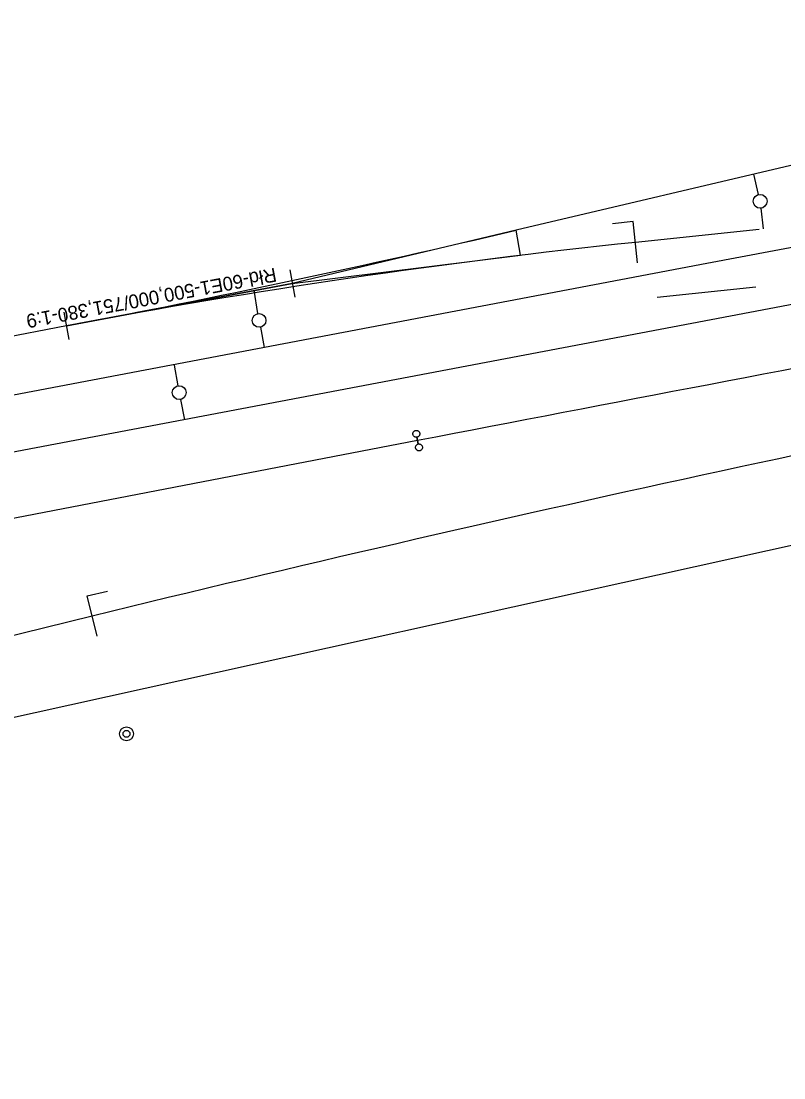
# Model space of a CAD drawing. Extents: x 6540402 to 6566579, y 5525343 to 5532423.
# Drawn here: x 6558407.9 to 6558463, y 5528815.2 to 5528891.5 of the extents above; entities that cross this region are included whole.
import ezdxf

# ---------------------------------------------------------------- set-up
doc = ezdxf.new("R2010")
doc.units = 0
for name, color, linetype in [('IR_ps_geometria', 7, 'Continuous'), ('TOR_PS_ODW-studnie betonowe', 7, 'Continuous'), ('TOR_PS_OPIS_T-symbole geometrii', 7, 'Continuous'), ('TOR_PS_OPIS_T-ukresy', 7, 'Continuous'), ('TOR_PS_T-rozjazdy projektowane', 7, 'Continuous'), ('TOR_PS_T-tory projektowane', 7, 'Continuous')]:
    doc.layers.add(name, color=color, linetype=linetype)

msp = doc.modelspace()

# ---------------------------------------------------------------- linework, layer by layer
at = {"layer": 'IR_ps_geometria'}
msp.add_lwpolyline([(6558436.522, 5528861.25), (6558436.569, 5528861.005), (6558436.602, 5528861.009), (6558436.634, 5528861.009), (6558436.667, 5528861.004), (6558436.698, 5528860.996), (6558436.728, 5528860.983), (6558436.757, 5528860.966), (6558436.782, 5528860.946), (6558436.805, 5528860.923), (6558436.825, 5528860.897), (6558436.841, 5528860.869), (6558436.854, 5528860.838), (6558436.862, 5528860.807), (6558436.866, 5528860.774), (6558436.866, 5528860.741), (6558436.861, 5528860.709), (6558436.853, 5528860.678), (6558436.84, 5528860.647), (6558436.823, 5528860.619), (6558436.803, 5528860.593), (6558436.78, 5528860.57), (6558436.754, 5528860.551), (6558436.725, 5528860.534), (6558436.695, 5528860.522), (6558436.664, 5528860.514), (6558436.631, 5528860.51), (6558436.598, 5528860.51), (6558436.566, 5528860.515), (6558436.534, 5528860.523), (6558436.504, 5528860.536), (6558436.476, 5528860.552), (6558436.45, 5528860.572), (6558436.427, 5528860.596), (6558436.408, 5528860.622), (6558436.391, 5528860.65), (6558436.379, 5528860.681), (6558436.371, 5528860.712), (6558436.367, 5528860.745), (6558436.367, 5528860.777), (6558436.371, 5528860.81), (6558436.38, 5528860.841), (6558436.393, 5528860.871), (6558436.409, 5528860.9), (6558436.429, 5528860.925), (6558436.453, 5528860.948), (6558436.479, 5528860.968), (6558436.507, 5528860.984), (6558436.538, 5528860.997), (6558436.569, 5528861.005), (6558436.475, 5528861.496), (6558436.442, 5528861.492), (6558436.41, 5528861.492), (6558436.377, 5528861.497), (6558436.346, 5528861.505), (6558436.316, 5528861.518), (6558436.287, 5528861.534), (6558436.262, 5528861.555), (6558436.239, 5528861.578), (6558436.219, 5528861.604), (6558436.203, 5528861.632), (6558436.19, 5528861.663), (6558436.182, 5528861.694), (6558436.178, 5528861.727), (6558436.178, 5528861.759), (6558436.183, 5528861.792), (6558436.191, 5528861.823), (6558436.204, 5528861.853), (6558436.221, 5528861.882), (6558436.241, 5528861.907), (6558436.264, 5528861.93), (6558436.29, 5528861.95), (6558436.318, 5528861.966), (6558436.349, 5528861.979), (6558436.38, 5528861.987), (6558436.413, 5528861.991), (6558436.446, 5528861.991), (6558436.478, 5528861.986), (6558436.509, 5528861.978), (6558436.54, 5528861.965), (6558436.568, 5528861.948), (6558436.594, 5528861.928), (6558436.617, 5528861.905), (6558436.636, 5528861.879), (6558436.652, 5528861.851), (6558436.665, 5528861.82), (6558436.673, 5528861.789), (6558436.677, 5528861.756), (6558436.677, 5528861.723), (6558436.672, 5528861.691), (6558436.664, 5528861.66), (6558436.651, 5528861.629), (6558436.635, 5528861.601), (6558436.614, 5528861.575), (6558436.591, 5528861.552), (6558436.565, 5528861.533), (6558436.537, 5528861.516), (6558436.506, 5528861.504), (6558436.475, 5528861.496)], close=True, dxfattribs=at)
msp.add_lwpolyline([(6558436.522, 5528861.25), (6558436.569, 5528861.005), (6558436.602, 5528861.009), (6558436.634, 5528861.009), (6558436.667, 5528861.004), (6558436.698, 5528860.996), (6558436.728, 5528860.983), (6558436.757, 5528860.966), (6558436.782, 5528860.946), (6558436.805, 5528860.923), (6558436.825, 5528860.897), (6558436.841, 5528860.869), (6558436.854, 5528860.838), (6558436.862, 5528860.807), (6558436.866, 5528860.774), (6558436.866, 5528860.741), (6558436.861, 5528860.709), (6558436.853, 5528860.678), (6558436.84, 5528860.647), (6558436.823, 5528860.619), (6558436.803, 5528860.593), (6558436.78, 5528860.57), (6558436.754, 5528860.551), (6558436.725, 5528860.534), (6558436.695, 5528860.522), (6558436.664, 5528860.514), (6558436.631, 5528860.51), (6558436.598, 5528860.51), (6558436.566, 5528860.515), (6558436.534, 5528860.523), (6558436.504, 5528860.536), (6558436.476, 5528860.552), (6558436.45, 5528860.572), (6558436.427, 5528860.596), (6558436.408, 5528860.622), (6558436.391, 5528860.65), (6558436.379, 5528860.681), (6558436.371, 5528860.712), (6558436.367, 5528860.745), (6558436.367, 5528860.777), (6558436.371, 5528860.81), (6558436.38, 5528860.841), (6558436.393, 5528860.871), (6558436.409, 5528860.9), (6558436.429, 5528860.925), (6558436.453, 5528860.948), (6558436.479, 5528860.968), (6558436.507, 5528860.984), (6558436.538, 5528860.997), (6558436.569, 5528861.005), (6558436.475, 5528861.496), (6558436.442, 5528861.492), (6558436.41, 5528861.492), (6558436.377, 5528861.497), (6558436.346, 5528861.505), (6558436.316, 5528861.518), (6558436.287, 5528861.534), (6558436.262, 5528861.555), (6558436.239, 5528861.578), (6558436.219, 5528861.604), (6558436.203, 5528861.632), (6558436.19, 5528861.663), (6558436.182, 5528861.694), (6558436.178, 5528861.727), (6558436.178, 5528861.759), (6558436.183, 5528861.792), (6558436.191, 5528861.823), (6558436.204, 5528861.853), (6558436.221, 5528861.882), (6558436.241, 5528861.907), (6558436.264, 5528861.93), (6558436.29, 5528861.95), (6558436.318, 5528861.966), (6558436.349, 5528861.979), (6558436.38, 5528861.987), (6558436.413, 5528861.991), (6558436.446, 5528861.991), (6558436.478, 5528861.986), (6558436.509, 5528861.978), (6558436.54, 5528861.965), (6558436.568, 5528861.948), (6558436.594, 5528861.928), (6558436.617, 5528861.905), (6558436.636, 5528861.879), (6558436.652, 5528861.851), (6558436.665, 5528861.82), (6558436.673, 5528861.789), (6558436.677, 5528861.756), (6558436.677, 5528861.723), (6558436.672, 5528861.691), (6558436.664, 5528861.66), (6558436.651, 5528861.629), (6558436.635, 5528861.601), (6558436.614, 5528861.575), (6558436.591, 5528861.552), (6558436.565, 5528861.533), (6558436.537, 5528861.516), (6558436.506, 5528861.504), (6558436.475, 5528861.496)], close=True, dxfattribs=at)
msp.add_lwpolyline([(6558436.522, 5528861.25), (6558436.569, 5528861.005), (6558436.602, 5528861.009), (6558436.634, 5528861.009), (6558436.667, 5528861.004), (6558436.698, 5528860.996), (6558436.728, 5528860.983), (6558436.757, 5528860.966), (6558436.782, 5528860.946), (6558436.805, 5528860.923), (6558436.825, 5528860.897), (6558436.841, 5528860.869), (6558436.854, 5528860.838), (6558436.862, 5528860.807), (6558436.866, 5528860.774), (6558436.866, 5528860.741), (6558436.861, 5528860.709), (6558436.853, 5528860.678), (6558436.84, 5528860.647), (6558436.823, 5528860.619), (6558436.803, 5528860.593), (6558436.78, 5528860.57), (6558436.754, 5528860.551), (6558436.725, 5528860.534), (6558436.695, 5528860.522), (6558436.664, 5528860.514), (6558436.631, 5528860.51), (6558436.598, 5528860.51), (6558436.566, 5528860.515), (6558436.534, 5528860.523), (6558436.504, 5528860.536), (6558436.476, 5528860.552), (6558436.45, 5528860.572), (6558436.427, 5528860.596), (6558436.408, 5528860.622), (6558436.391, 5528860.65), (6558436.379, 5528860.681), (6558436.371, 5528860.712), (6558436.367, 5528860.745), (6558436.367, 5528860.777), (6558436.371, 5528860.81), (6558436.38, 5528860.841), (6558436.393, 5528860.871), (6558436.409, 5528860.9), (6558436.429, 5528860.925), (6558436.453, 5528860.948), (6558436.479, 5528860.968), (6558436.507, 5528860.984), (6558436.538, 5528860.997), (6558436.569, 5528861.005), (6558436.475, 5528861.496), (6558436.442, 5528861.492), (6558436.41, 5528861.492), (6558436.377, 5528861.497), (6558436.346, 5528861.505), (6558436.316, 5528861.518), (6558436.287, 5528861.534), (6558436.262, 5528861.555), (6558436.239, 5528861.578), (6558436.219, 5528861.604), (6558436.203, 5528861.632), (6558436.19, 5528861.663), (6558436.182, 5528861.694), (6558436.178, 5528861.727), (6558436.178, 5528861.759), (6558436.183, 5528861.792), (6558436.191, 5528861.823), (6558436.204, 5528861.853), (6558436.221, 5528861.882), (6558436.241, 5528861.907), (6558436.264, 5528861.93), (6558436.29, 5528861.95), (6558436.318, 5528861.966), (6558436.349, 5528861.979), (6558436.38, 5528861.987), (6558436.413, 5528861.991), (6558436.446, 5528861.991), (6558436.478, 5528861.986), (6558436.509, 5528861.978), (6558436.54, 5528861.965), (6558436.568, 5528861.948), (6558436.594, 5528861.928), (6558436.617, 5528861.905), (6558436.636, 5528861.879), (6558436.652, 5528861.851), (6558436.665, 5528861.82), (6558436.673, 5528861.789), (6558436.677, 5528861.756), (6558436.677, 5528861.723), (6558436.672, 5528861.691), (6558436.664, 5528861.66), (6558436.651, 5528861.629), (6558436.635, 5528861.601), (6558436.614, 5528861.575), (6558436.591, 5528861.552), (6558436.565, 5528861.533), (6558436.537, 5528861.516), (6558436.506, 5528861.504), (6558436.475, 5528861.496)], close=True, dxfattribs=at)
msp.add_lwpolyline([(6558436.522, 5528861.25), (6558436.569, 5528861.005), (6558436.602, 5528861.009), (6558436.634, 5528861.009), (6558436.667, 5528861.004), (6558436.698, 5528860.996), (6558436.728, 5528860.983), (6558436.757, 5528860.966), (6558436.782, 5528860.946), (6558436.805, 5528860.923), (6558436.825, 5528860.897), (6558436.841, 5528860.869), (6558436.854, 5528860.838), (6558436.862, 5528860.807), (6558436.866, 5528860.774), (6558436.866, 5528860.741), (6558436.861, 5528860.709), (6558436.853, 5528860.678), (6558436.84, 5528860.647), (6558436.823, 5528860.619), (6558436.803, 5528860.593), (6558436.78, 5528860.57), (6558436.754, 5528860.551), (6558436.725, 5528860.534), (6558436.695, 5528860.522), (6558436.664, 5528860.514), (6558436.631, 5528860.51), (6558436.598, 5528860.51), (6558436.566, 5528860.515), (6558436.534, 5528860.523), (6558436.504, 5528860.536), (6558436.476, 5528860.552), (6558436.45, 5528860.572), (6558436.427, 5528860.596), (6558436.408, 5528860.622), (6558436.391, 5528860.65), (6558436.379, 5528860.681), (6558436.371, 5528860.712), (6558436.367, 5528860.745), (6558436.367, 5528860.777), (6558436.371, 5528860.81), (6558436.38, 5528860.841), (6558436.393, 5528860.871), (6558436.409, 5528860.9), (6558436.429, 5528860.925), (6558436.453, 5528860.948), (6558436.479, 5528860.968), (6558436.507, 5528860.984), (6558436.538, 5528860.997), (6558436.569, 5528861.005), (6558436.475, 5528861.496), (6558436.442, 5528861.492), (6558436.41, 5528861.492), (6558436.377, 5528861.497), (6558436.346, 5528861.505), (6558436.316, 5528861.518), (6558436.287, 5528861.534), (6558436.262, 5528861.555), (6558436.239, 5528861.578), (6558436.219, 5528861.604), (6558436.203, 5528861.632), (6558436.19, 5528861.663), (6558436.182, 5528861.694), (6558436.178, 5528861.727), (6558436.178, 5528861.759), (6558436.183, 5528861.792), (6558436.191, 5528861.823), (6558436.204, 5528861.853), (6558436.221, 5528861.882), (6558436.241, 5528861.907), (6558436.264, 5528861.93), (6558436.29, 5528861.95), (6558436.318, 5528861.966), (6558436.349, 5528861.979), (6558436.38, 5528861.987), (6558436.413, 5528861.991), (6558436.446, 5528861.991), (6558436.478, 5528861.986), (6558436.509, 5528861.978), (6558436.54, 5528861.965), (6558436.568, 5528861.948), (6558436.594, 5528861.928), (6558436.617, 5528861.905), (6558436.636, 5528861.879), (6558436.652, 5528861.851), (6558436.665, 5528861.82), (6558436.673, 5528861.789), (6558436.677, 5528861.756), (6558436.677, 5528861.723), (6558436.672, 5528861.691), (6558436.664, 5528861.66), (6558436.651, 5528861.629), (6558436.635, 5528861.601), (6558436.614, 5528861.575), (6558436.591, 5528861.552), (6558436.565, 5528861.533), (6558436.537, 5528861.516), (6558436.506, 5528861.504), (6558436.475, 5528861.496)], close=True, dxfattribs=at)
at = {"layer": 'TOR_PS_ODW-studnie betonowe'}
for radius in [0.5, 0.25]:
    msp.add_circle((6558415.486, 5528840.078), radius, dxfattribs=at)
at = {"layer": 'TOR_PS_OPIS_T-symbole geometrii'}
for p, q in [((6558452.1, 5528877.06), (6558450.608, 5528876.904)), ((6558452.412, 5528874.076), (6558452.1, 5528877.06)), ((6558412.649, 5528850.032), (6558414.106, 5528850.388)), ((6558413.362, 5528847.118), (6558412.649, 5528850.032))]:
    msp.add_line(p, q, dxfattribs=at)
at = {"layer": 'TOR_PS_OPIS_T-ukresy'}
for p, q in [((6558461.151, 5528879.015), (6558460.805, 5528880.485)), ((6558461.319, 5528878.031), (6558461.476, 5528876.53)), ((6558424.983, 5528870.423), (6558424.713, 5528872.102)), ((6558425.156, 5528869.438), (6558425.435, 5528867.965)), ((6558419.208, 5528865.207), (6558418.946, 5528866.694)), ((6558419.388, 5528864.223), (6558419.667, 5528862.749))]:
    msp.add_line(p, q, dxfattribs=at)
msp.add_lwpolyline([(6558427.467, 5528872.602), (6558443.958, 5528874.628), (6558443.636, 5528876.437)], dxfattribs=at)
for centre in [(6558461.266, 5528878.529), (6558425.063, 5528869.93), (6558419.295, 5528864.714)]:
    msp.add_circle(centre, 0.5, dxfattribs=at)
at = {"layer": 'TOR_PS_T-rozjazdy projektowane'}
for p, q in [((6558427.282, 5528873.584), (6558427.652, 5528871.619)), ((6558410.953, 5528870.512), (6558411.323, 5528868.547))]:
    msp.add_line(p, q, dxfattribs=at)
msp.add_lwpolyline([(6558443.636, 5528876.437), (6558427.467, 5528872.602), (6558411.138, 5528869.529), (6558427.467, 5528872.602), (6558443.958, 5528874.628)], close=True, dxfattribs=at)
at = {"layer": 'TOR_PS_T-tory projektowane'}
for p, q in [((6558571.547, 5528891.538), (6557352.881, 5528660.537)), ((6558487.458, 5528886.769), (6558443.636, 5528876.437)), ((6558498.399, 5528881.795), (6558457.417, 5528874.027)), ((6558461.188, 5528876.499), (6558452.256, 5528875.565)), ((6558457.417, 5528874.027), (6558406.817, 5528864.435)), ((6558460.965, 5528872.335), (6558453.83, 5528871.589)), ((6558411.138, 5528869.529), (6558400.489, 5528867.511)), ((6558436.522, 5528861.25), (6558369.682, 5528848.4)), ((6558464.527, 5528853.896), (6558317.161, 5528821.298)), ((6558413.005, 5528848.575), (6558360.905, 5528835.82))]:
    msp.add_line(p, q, dxfattribs=at)
for centre, radius, start, end in [((6564657.209, 5496503.785), 32950, 100.733239, 100.8822778), ((6558271.204, 5529607.764), 751.38, 280.73312, 283.266871), ((6558504.257, 5528378.277), 500, 95.9696, 100.73326), ((6558820.806, 5527182.764), 1715, 100.733239, 103.755807)]:
    msp.add_arc(centre, radius, start, end, dxfattribs=at)

# ---------------------------------------------------------------- texts
at = {"layer": 'TOR_PS_T-rozjazdy projektowane'}
msp.add_text('Rłd-60E1-500,000/751,380-1:9', height=1, rotation=190.65595, dxfattribs=at).set_placement((6558426.217, 5528873.736))

doc.saveas('drawing.dxf')
